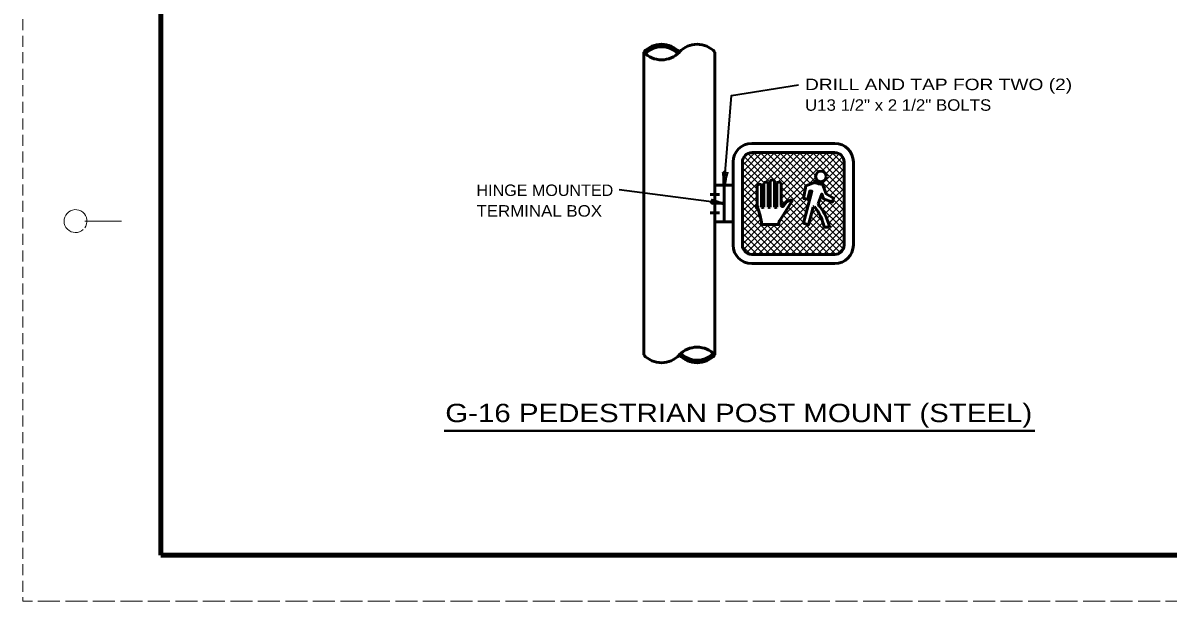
# Model space of a CAD drawing. Extents: x -286 to 394, y -156 to 284.
# Drawn here: x -286.4 to -36.6, y -155.6 to -29.5 of the extents above; entities that cross this region are included whole.
import ezdxf
from ezdxf.enums import TextEntityAlignment as Align

# ---------------------------------------------------------------- set-up
doc = ezdxf.new("R2010")
doc.units = 0
doc.header["$LTSCALE"] = 0.8
doc.header["$PDMODE"] = 32
doc.header["$PDSIZE"] = 0.4
doc.linetypes.add('LONG_DASHED', pattern=[7.5, 6, -1.5])
doc.linetypes.add('MEDIUM_DASHED', pattern=[4.5, 3, -1.5])
doc.layers.add('1', color=7, linetype='Continuous', lineweight=53)
doc.layers.add('61', color=7, linetype='Continuous', lineweight=35)

msp = doc.modelspace()

# ---------------------------------------------------------------- linework, layer by layer
at = {"layer": '1', "linetype": 'MEDIUM_DASHED', "lineweight": 13}
msp.add_line((-286.3491, 284.4627), (-286.4091, -155.5772), dxfattribs=at)
at = {"layer": '1'}
for p, q in [((-150.9551, -101.9196), (-150.9551, -35.8937)), ((-135.4551, -35.8937), (-135.4551, -101.9196)), ((-127.4351, -55.8167), (-109.2951, -55.8167)), ((-131.4551, -77.9767), (-131.4551, -59.8367)), ((-129.4551, -59.8367), (-129.4551, -77.9767)), ((-109.2951, -57.8167), (-127.4351, -57.8167)), ((-107.2751, -77.9767), (-107.2751, -59.8367)), ((-105.2551, -77.9767), (-105.2551, -59.8367)), ((-131.4551, -64.9067), (-135.4551, -64.9067)), ((-133.4551, -64.9067), (-133.4551, -72.9067)), ((-124.8151, -69.6967), (-124.8151, -64.4967)), ((-123.8551, -64.4967), (-123.8551, -69.6967)), ((-123.3951, -69.6967), (-123.3951, -64.0167)), ((-122.4551, -64.0167), (-122.4551, -69.6967)), ((-121.9751, -69.6967), (-121.9751, -64.4967)), ((-121.0351, -64.4967), (-121.0351, -69.3367)), ((-134.4551, -66.9067), (-136.4551, -66.9067)), ((-126.2351, -69.6967), (-126.2351, -64.9567)), ((-125.2751, -64.9567), (-125.2751, -69.6967)), ((-118.7351, -68.5567), (-121.1151, -72.3767)), ((-134.4551, -70.9067), (-136.4551, -70.9067)), ((-131.4551, -72.9067), (-135.4551, -72.9067)), ((-110.4751, -74.0367), (-111.6151, -74.0367)), ((-127.4351, -79.9967), (-109.2951, -79.9967)), ((-127.4351, -82.0167), (-109.2951, -82.0167))]:
    msp.add_line(p, q, dxfattribs=at)
at = {"layer": '1', "lineweight": 25}
for p, q in [((-129.4551, -60.6167), (-126.6551, -57.8167)), ((-129.4551, -62.0567), (-125.2151, -57.8167)), ((-129.4551, -63.4767), (-123.7951, -57.8167)), ((-129.4551, -64.8967), (-122.3751, -57.8167)), ((-129.4551, -66.3167), (-120.9351, -57.8167)), ((-129.4551, -67.7567), (-119.5151, -57.8167)), ((-124.7351, -64.3967), (-129.4351, -59.6967)), ((-129.2551, -59.0167), (-128.2551, -57.9967)), ((-123.3951, -64.3167), (-129.0551, -58.6567)), ((-121.8751, -64.3967), (-128.2751, -58.0167)), ((-115.2151, -69.6367), (-127.0351, -57.8167)), ((-116.0551, -67.3767), (-125.6151, -57.8167)), ((-124.5551, -64.2967), (-118.0951, -57.8167)), ((-115.8351, -66.1567), (-124.1751, -57.8167)), ((-115.5551, -65.0367), (-122.7551, -57.8167)), ((-122.6751, -63.8167), (-116.6751, -57.8167)), ((-121.6951, -64.2767), (-115.2351, -57.8167)), ((-114.5351, -64.6167), (-121.3351, -57.8167)), ((-121.0351, -65.0367), (-113.8151, -57.8167)), ((-121.0351, -66.4567), (-112.3951, -57.8167)), ((-121.0351, -67.8767), (-110.9751, -57.8167)), ((-121.0351, -69.3167), (-109.5351, -57.8167)), ((-113.4751, -64.2567), (-119.8951, -57.8167)), ((-113.4751, -62.8367), (-118.4751, -57.8167)), ((-112.8751, -61.9967), (-117.0551, -57.8167)), ((-107.2751, -66.1767), (-115.6351, -57.8167)), ((-107.2751, -64.7567), (-114.1951, -57.8167)), ((-107.2751, -63.3167), (-112.7751, -57.8167)), ((-112.1751, -61.8967), (-108.3551, -58.0567)), ((-112.1151, -64.6767), (-107.2751, -59.8367)), ((-107.2751, -61.8967), (-111.3551, -57.8167)), ((-111.3351, -62.4767), (-107.5951, -58.7367)), ((-107.2751, -60.4767), (-109.9151, -57.8167)), ((-107.6351, -58.6767), (-108.1151, -58.2167)), ((-125.8351, -64.7167), (-129.4551, -61.1167)), ((-111.6151, -65.5967), (-107.2751, -61.2567)), ((-126.2351, -65.7567), (-129.4551, -62.5367)), ((-126.2351, -67.1767), (-129.4551, -63.9567)), ((-125.2751, -65.0167), (-124.8151, -64.5367)), ((-123.8551, -65.0167), (-123.3951, -64.5367)), ((-122.4551, -65.0167), (-121.9751, -64.5567)), ((-115.1551, -64.8767), (-113.4751, -63.1767)), ((-113.2751, -64.4167), (-112.8751, -64.0167)), ((-107.2751, -69.0367), (-112.1751, -64.1367)), ((-107.2751, -67.5967), (-111.3351, -63.5367)), ((-111.2351, -66.6367), (-107.2751, -62.6767)), ((-110.3951, -67.2367), (-107.2751, -64.1167)), ((-126.2351, -68.6167), (-129.4551, -65.3767)), ((-129.4551, -69.1767), (-126.2351, -65.9567)), ((-125.9951, -70.2567), (-129.4551, -66.8167)), ((-129.4551, -70.5967), (-126.2351, -67.3767)), ((-124.8151, -65.7567), (-125.2751, -65.2767)), ((-125.2751, -66.4367), (-124.8151, -65.9567)), ((-124.8151, -67.1767), (-125.2751, -66.6967)), ((-125.2751, -67.8567), (-124.8151, -67.3967)), ((-123.3951, -65.7367), (-123.8551, -65.2767)), ((-123.8551, -66.4367), (-123.3951, -65.9767)), ((-123.3951, -67.1567), (-123.8551, -66.6967)), ((-123.8551, -67.8767), (-123.3951, -67.3967)), ((-121.9751, -65.7367), (-122.4551, -65.2567)), ((-122.4551, -66.4567), (-121.9751, -65.9767)), ((-121.9751, -67.1567), (-122.4551, -66.6767)), ((-122.4551, -67.8767), (-121.9751, -67.3967)), ((-115.5151, -70.7767), (-121.0351, -65.2567)), ((-119.3551, -68.3567), (-121.0351, -66.6767)), ((-120.8951, -72.0167), (-116.0151, -67.1567)), ((-118.6551, -68.3767), (-115.7151, -65.4167)), ((-115.1751, -67.7367), (-114.5151, -67.0767)), ((-114.6151, -67.3967), (-114.9751, -67.0167)), ((-114.3151, -66.2767), (-114.3551, -66.2367)), ((-112.5351, -67.9567), (-111.9351, -67.3567)), ((-112.0151, -67.1367), (-112.1751, -66.9767)), ((-111.5151, -71.1967), (-107.2751, -66.9567)), ((-110.5951, -67.1167), (-111.3151, -66.4167)), ((-109.6351, -67.8967), (-107.2751, -65.5367)), ((-125.4351, -72.2367), (-129.4551, -68.2367)), ((-129.4551, -72.0367), (-126.2351, -68.7967)), ((-119.1151, -79.9967), (-129.4551, -69.6567)), ((-127.4351, -79.9967), (-115.3551, -67.8967)), ((-126.0151, -79.9967), (-115.0551, -69.0367)), ((-124.8151, -68.5967), (-125.2751, -68.1167)), ((-125.2751, -69.2767), (-124.8151, -68.8167)), ((-125.0551, -69.7767), (-125.2751, -69.5567)), ((-123.3951, -68.5967), (-123.8551, -68.1167)), ((-123.8551, -69.2967), (-123.3951, -68.8167)), ((-123.6351, -69.7767), (-123.8551, -69.5367)), ((-121.9751, -68.5767), (-122.4551, -68.1167)), ((-122.4551, -69.2967), (-121.9751, -68.8367)), ((-122.2151, -69.7767), (-122.4551, -69.5367)), ((-120.1751, -68.9567), (-121.0351, -68.0967)), ((-116.1151, -73.0167), (-119.4351, -69.6967)), ((-115.8151, -71.8967), (-118.8951, -68.8167)), ((-114.9151, -68.5167), (-115.5551, -67.8767)), ((-113.3151, -70.1167), (-113.8351, -69.5967)), ((-107.2751, -74.7367), (-112.8951, -69.1167)), ((-112.6551, -69.4767), (-111.2351, -68.0767)), ((-107.2751, -73.2967), (-112.5551, -68.0167)), ((-112.0351, -70.2967), (-110.1951, -68.4567)), ((-111.0551, -72.1767), (-107.2751, -68.3767)), ((-107.2751, -71.8767), (-110.9751, -68.1767)), ((-110.6951, -73.2367), (-107.2751, -69.8167)), ((-107.2751, -70.4567), (-109.6751, -68.0567)), ((-129.4551, -73.4567), (-126.0751, -70.0767)), ((-120.5351, -79.9967), (-129.4551, -71.0967)), ((-129.4551, -74.8767), (-125.7151, -71.1367)), ((-129.4551, -76.2967), (-125.4351, -72.2967)), ((-124.5951, -79.9967), (-115.5751, -70.9767)), ((-113.4151, -79.9967), (-121.0751, -72.3367)), ((-111.9751, -79.9967), (-120.5351, -71.4567)), ((-120.3151, -79.9967), (-112.2951, -71.9767)), ((-110.5551, -79.9967), (-119.9751, -70.5767)), ((-116.0351, -79.9967), (-107.2751, -71.2367)), ((-114.9951, -73.2567), (-112.7551, -71.0167)), ((-107.4551, -78.8167), (-114.5751, -71.6967)), ((-114.4751, -71.3167), (-113.2951, -70.1367)), ((-111.9351, -72.9167), (-114.2751, -70.5767)), ((-121.9551, -79.9967), (-129.4551, -72.5167)), ((-129.4551, -77.7367), (-125.1951, -73.4767)), ((-123.3951, -79.9967), (-129.4551, -73.9367)), ((-129.2151, -78.9167), (-123.7551, -73.4767)), ((-128.5351, -79.6767), (-122.3351, -73.4767)), ((-117.6751, -79.9967), (-124.2151, -73.4767)), ((-123.1551, -79.9967), (-116.0951, -72.9167)), ((-116.2551, -79.9967), (-122.7951, -73.4767)), ((-121.7351, -79.9967), (-115.2551, -73.5167)), ((-114.8351, -79.9967), (-121.4951, -73.3367)), ((-118.8951, -79.9967), (-111.8951, -73.0167)), ((-117.4551, -79.9967), (-111.5151, -74.0367)), ((-109.1551, -79.9767), (-115.8151, -73.3167)), ((-108.0951, -79.5967), (-114.8751, -72.8167)), ((-114.6151, -79.9967), (-107.2751, -72.6567)), ((-113.1751, -79.9967), (-107.2751, -74.0767)), ((-107.2751, -76.1567), (-110.9351, -72.4967)), ((-107.2751, -77.5767), (-110.8151, -74.0367)), ((-124.8151, -79.9967), (-129.4551, -75.3567)), ((-126.2351, -79.9967), (-129.4551, -76.7967)), ((-111.7551, -79.9967), (-107.2751, -75.5167)), ((-110.3351, -79.9967), (-107.2751, -76.9367)), ((-127.6751, -79.9767), (-129.4151, -78.2367)), ((-108.8551, -79.9567), (-107.3351, -78.4167))]:
    msp.add_line(p, q, dxfattribs=at)
at = {"layer": '1', "lineweight": 35}
msp.add_line((-133.4551, -68.9067), (-156.375, -65.907), dxfattribs=at)
at = {"layer": '1', "lineweight": 40}
msp.add_line((-194.5117, -118.4416), (-65.6312, -118.4416), dxfattribs=at)
at = {"layer": '1', "lineweight": 35}
msp.add_lwpolyline([(-133.4551, -64.9067), (-131.8003, -45.3532), (-117.1921, -43.0315)], dxfattribs=at)
at = {"layer": '1'}
for points in [[(-114.0551, -69.7167), (-115.0751, -73.5767), (-116.1551, -73.1767), (-114.2951, -66.2367), (-114.7551, -66.1567), (-115.2151, -67.9367), (-116.1151, -67.7767), (-115.6551, -65.0567), (-113.5351, -64.2167)], [(-111.9551, -64.6567), (-111.1751, -66.7967), (-109.5751, -67.7167), (-109.8151, -68.5967), (-111.7351, -67.8967), (-112.1351, -66.8167), (-112.9151, -68.9767)], [(-121.4951, -72.9967), (-121.4951, -73.4767), (-125.2751, -73.4767)]]:
    msp.add_lwpolyline(points, dxfattribs=at)
msp.add_circle((-112.3461, -63.0121), 1.1435, dxfattribs=at)
for centre, radius, start, end in [((-147.0801, -39.4888), 5.2962, 42.97503, 137.02497), ((-147.0801, -40.0444), 5.2962, 47.11243, 132.88757), ((-139.3419, -39.4888), 5.2962, 42.97503, 137.02497), ((-147.0801, -32.2834), 5.2962, 222.97503, 317.02497), ((-127.4321, -59.8389), 4.032, 90, 180), ((-109.2881, -59.8389), 4.032, 0, 90), ((-127.4321, -59.8389), 2.016, 90, 180), ((-109.2881, -59.8389), 2.016, 0, 90), ((-125.7531, -65.2647), 0.5588, 32.26726, 147.73274), ((-124.3356, -64.7922), 0.5588, 32.26726, 147.73274), ((-122.9181, -64.3197), 0.5588, 32.26726, 147.73274), ((-121.5006, -64.7922), 0.5588, 32.26726, 147.73274), ((-112.3544, -63.0468), 1.6507, 224.78621, 284.15055), ((-136.433, -74.2513), 11.1797, 4.00065, 24.07184), ((-125.0444, -69.4148), 0.3638, 229.49744, 310.50256), ((-123.6269, -69.4148), 0.3638, 229.49744, 310.50256), ((-122.2094, -69.4148), 0.3638, 229.49744, 310.50256), ((-120.7351, -69.2567), 0.3058, 196.62901, 346.9737), ((-118.2316, -70.6536), 2.5745, 107.58203, 148.94869), ((-118.8842, -68.3928), 0.2304, 313.16859, 122.89183), ((-113.4976, -70.4696), 0.9383, 102.87116, 125.96864), ((-122.6845, -76.4661), 11.3299, 12.34164, 37.58932), ((-112.2341, -68.9601), 0.6797, 180.88666, 241.05185), ((-121.3752, -76.3889), 11.1515, 12.13626, 37.79469), ((-120.5364, -73.1649), 0.9774, 125.78093, 170.21865), ((-127.4321, -77.9829), 4.032, 180, 270), ((-127.4321, -77.9829), 2.016, 180, 270), ((-109.2881, -77.9829), 4.032, 270, 0), ((-109.2881, -77.9829), 2.016, 270, 0), ((-147.0801, -98.3092), 5.2962, 222.97503, 317.02497), ((-139.3419, -105.5146), 5.2962, 42.97503, 137.02497), ((-139.3419, -98.3092), 5.2962, 222.97503, 317.02497), ((-139.3419, -97.7536), 5.2962, 227.11243, 312.88757)]:
    msp.add_arc(centre, radius, start, end, dxfattribs=at)
at = {"layer": '1', "lineweight": 60}
for centre, major_axis, ratio, start_param, end_param in [((-133.6384, -63.7961), (0.005, -1.7925), 0.122415, 0.89635335, 3.14159265), ((-133.1498, -63.808), (-0.3231, -1.7354), 0.07063, 3.14071475, 5.41810995), ((-134.5729, -69.039), (1.7909, -0.0769), 0.122415, 0.89635335, 3.14159265), ((-134.5386, -68.5514), (1.7188, -0.4021), 0.07063, 3.14071475, 5.41810995)]:
    msp.add_ellipse(centre, major_axis=major_axis, ratio=ratio, start_param=start_param, end_param=end_param, dxfattribs=at)
at = {"layer": '1'}
for p in [(-113.5351, -64.2167), (-126.2351, -69.6967)]:
    msp.add_point(p, dxfattribs=at)
at = {"layer": '61', "lineweight": 13}
msp.add_line((-272.9091, -72.7373), (-264.9291, -72.7373), dxfattribs=at)
at = {"layer": '61', "lineweight": 158}
msp.add_line((382.7109, -145.5772), (-256.3491, -145.5572), dxfattribs=at)
at = {"layer": '61', "linetype": 'LONG_DASHED', "lineweight": 13}
msp.add_line((393.6509, -155.5572), (-286.4091, -155.5772), dxfattribs=at)
at = {"layer": '61', "lineweight": 158}
msp.add_lwpolyline([(382.6909, 274.4627), (-256.3491, 274.4627), (-256.3491, -145.5572)], dxfattribs=at)
at = {"layer": '61', "lineweight": 13}
msp.add_arc((-274.9313, -72.736), 2.5, 323.13009, 312.31439, dxfattribs=at)

# ---------------------------------------------------------------- texts
at = {"layer": '1'}
for s, width, p in [('DRILL AND TAP FOR TWO (2)', 1.25, (-115.8039, -44.1846)), ('U13 1/2" x 2 1/2" BOLTS', 1.1, (-115.8039, -48.6846)), ('HINGE MOUNTED', 1.05, (-187.4592, -67.2628)), ('TERMINAL BOX', 1.1, (-187.4592, -71.7628))]:
    msp.add_text(s, height=2.5, dxfattribs=dict(at, width=width)).set_placement(p)
at = {"layer": '1', "width": 1.2}
msp.add_text('G-16 PEDESTRIAN POST MOUNT (STEEL)', height=4, dxfattribs=at).set_placement((-130.2488, -116.5643), align=Align.CENTER)

doc.saveas('drawing.dxf')
